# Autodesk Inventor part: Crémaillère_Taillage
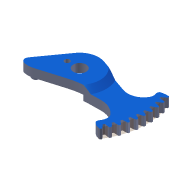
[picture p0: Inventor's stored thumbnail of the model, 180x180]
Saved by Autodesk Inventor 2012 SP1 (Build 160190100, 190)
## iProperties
Created: 2014-12
Part Number: Crémaillère_Taillage
Material: Default
Document SubType Name: Modeling
Designer: Bruno
Density: 1 g/cm^3
Mass: 8.41821 g
Surface Area: 46.446 cm^2
Volume: 8.41821 cm^3
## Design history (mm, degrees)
node "Crémaillère_Taillage1"
sketch "Esquisse1"
  geometry: C1 r 6.757 at (52.405, -4.519) reference; A1 r 14.635 centre (42.992, 2.923) between (43.877, 17.531) and (38.203, 16.752) reference; A2 r 14.635 centre (41.649, -11.053) between (36.679, -24.818) and (39.738, -25.563) reference; A3 r 43.86 centre (0, 0) between (41.882, 13.022) and (41.494, 14.209) reference; A4 r 45.843 centre (0, 0) between (38.239, -25.285) and (42.353, 17.544)
  constraints: 4 point on circle, 1 centre point, 1 coincident, 1 tangent
  dimensions: "d2" = 45.84301 radius of A4 (derived)
feature "SrfExtrusion1" sketch "Esquisse1" dims "d0" = 7, "d1" = 0
node "Crémaillère_Taillage"
node "Base1"
node "Référence1"
body "Srf1"
